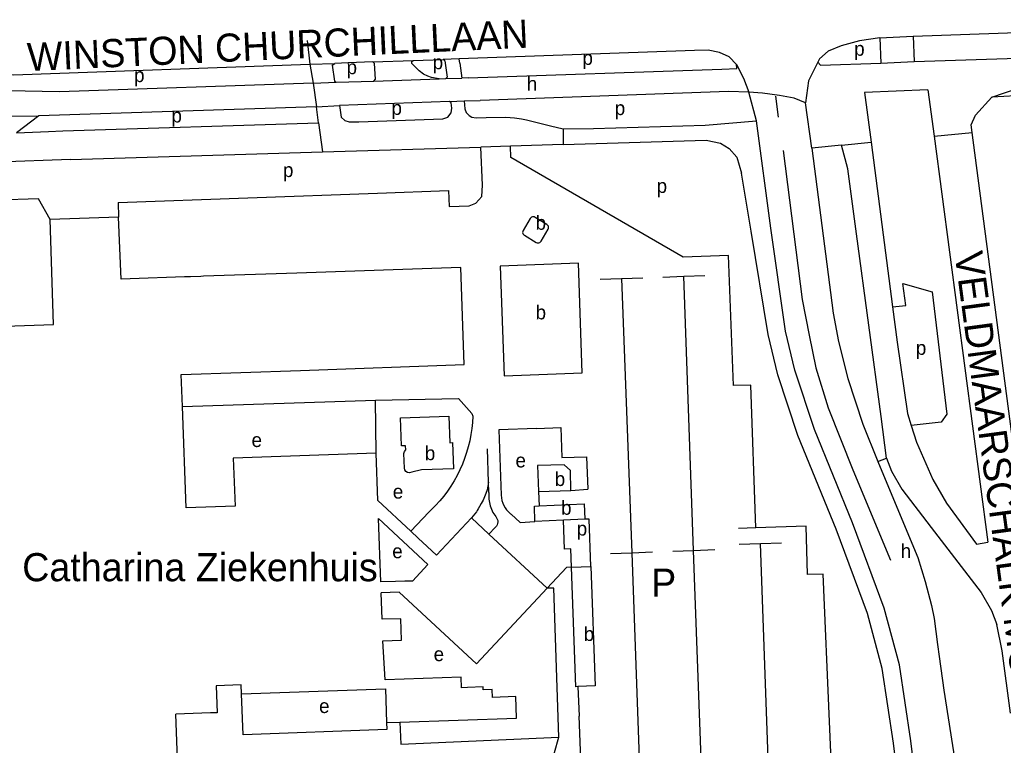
# Model space of a CAD drawing. Extents: x 159294 to 161936, y 384538 to 386517.
# Drawn here: x 160840.4 to 161120.1, y 386277.4 to 386483.9 of the extents above; entities that cross this region are included whole.
import ezdxf

# ---------------------------------------------------------------- set-up
doc = ezdxf.new("R2010")
doc.units = 0
for name, color, linetype in [('BLT_Basislijn', 7, 'Continuous'), ('BLT_Bebouwing', 7, 'Continuous'), ('BLT_Bebouwing_beschrifting', 7, 'Continuous'), ('BLT_Centroide', 7, 'Continuous'), ('BLT_Straatnaam_hoofdweg', 7, 'Continuous'), ('BLT_Tekst_parkeren', 7, 'Continuous'), ('BLT_Vlakafsluiter', 7, 'Continuous')]:
    doc.layers.add(name, color=color, linetype=linetype)

msp = doc.modelspace()

# ---------------------------------------------------------------- linework, layer by layer
at = {"layer": 'BLT_Basislijn'}
for p, q in [((161085.03, 386478.68), (161094.48, 386479.13)), ((161094.48, 386479.13), (161094.83, 386471.96)), ((161085.03, 386478.68), (161085.34, 386471.53)), ((160922.92, 386471.2), (160930.01, 386471.41)), ((160929.31, 386470.96), (160930.01, 386471.41)), ((160940.82, 386471.84), (160933.85, 386471.57)), ((160940.82, 386471.84), (160952.31, 386472.22)), ((160952.31, 386472.22), (160960.85, 386472.53)), ((160965.42, 386472.68), (160960.85, 386472.53)), ((160961.33, 386472.16), (160960.85, 386472.53)), ((160961.33, 386472.16), (160962.02, 386467.55)), ((160965.58, 386471.53), (160965.42, 386472.68)), ((161067.39, 386471.8), (161068.19, 386470.95)), ((161068.19, 386470.95), (161085.34, 386471.53)), ((161085.34, 386471.53), (161094.83, 386471.96)), ((160923.87, 386465.82), (160930.39, 386466.04)), ((160930.39, 386466.04), (160941.1, 386466.4)), ((160941.1, 386466.4), (160959.76, 386467.06)), ((160959.76, 386467.06), (160961.59, 386467.13)), ((160962.02, 386467.55), (160961.59, 386467.13)), ((160961.59, 386467.13), (160966.18, 386467.26)), ((160967.93, 386467.32), (160966.18, 386467.26)), ((161049.99, 386455.07), (161047.78, 386463.2)), ((161055.34, 386462.07), (161056.13, 386456.14)), ((161098.68, 386463.93), (161100.43, 386450.73)), ((160924.85, 386459.04), (160931.4, 386459.49)), ((160962.67, 386460.58), (160931.4, 386459.49)), ((160962.67, 386460.58), (160966.83, 386460.73)), ((160966.83, 386460.73), (160971.37, 386460.89)), ((161065.67, 386447.34), (161063.85, 386460.23)), ((160838.19, 386456.38), (160845.85, 386456.53)), ((161111.25, 386451.79), (161110.97, 386453.95)), ((160994.99, 386452.82), (160994.99, 386448.34)), ((161124.87, 386348.64), (161111.25, 386451.79)), ((160994.99, 386448.34), (160979.98, 386447.9)), ((161082.53, 386448.98), (161088.67, 386402.18)), ((161100.43, 386450.73), (161115.75, 386335.22)), ((160854.9, 386444.07), (160926.51, 386446.24)), ((160926.51, 386446.24), (160971.6, 386447.61)), ((160979.98, 386447.9), (160971.6, 386447.61)), ((160972.05, 386436.82), (160971.6, 386447.61)), ((160854.9, 386444.07), (160765.92, 386440.98)), ((160868.43, 386431.86), (160942.16, 386434.52)), ((160971.82, 386433.6), (160972.05, 386436.82)), ((160845.82, 386432.89), (160832.39, 386432.44)), ((160849.06, 386426.97), (160845.82, 386432.89)), ((160868.43, 386431.86), (160868.58, 386427.65)), ((160968.21, 386430.89), (160970.1, 386431.69)), ((160970.1, 386431.69), (160971.82, 386433.6)), ((161005.52, 386410.05), (161011.57, 386410.25)), ((161011.57, 386410.25), (161017.62, 386410.46)), ((161011.57, 386410.25), (161014.46, 386332.22)), ((161023.31, 386410.64), (161029.25, 386410.85)), ((161029.25, 386410.85), (161035.22, 386411.05)), ((161032.08, 386332.89), (161029.25, 386410.85)), ((161088.67, 386402.18), (161089.99, 386392.15)), ((160886.71, 386373.83), (160941.65, 386375.63)), ((160941.79, 386360.54), (160941.65, 386375.63)), ((160987.36, 386367.58), (160994.29, 386367.84)), ((160973.72, 386352.27), (160973.46, 386361.73)), ((160973.8, 386349.38), (160973.72, 386352.27)), ((160997.2, 386349.92), (161001.95, 386350.3)), ((160956.76, 386343.75), (160951.62, 386338.37)), ((160974.97, 386343.67), (160975.81, 386342.49)), ((160975.65, 386339.38), (160973.86, 386337.5)), ((161049.76, 386339.29), (161044.82, 386339.11)), ((161045.01, 386334.63), (161051.06, 386334.82)), ((161051.06, 386334.82), (161057.1, 386335.01)), ((161054.18, 386249.31), (161051.06, 386334.82)), ((161008.45, 386331.99), (161014.46, 386332.22)), ((161014.46, 386332.22), (161020.4, 386332.44)), ((161014.46, 386332.22), (161017.59, 386247.52)), ((161026.14, 386332.67), (161032.08, 386332.89)), ((161032.08, 386332.89), (161038.09, 386333.11)), ((161035.12, 386248.99), (161032.08, 386332.89)), ((161000.07, 386270.62), (160999.49, 386285.69))]:
    msp.add_line(p, q, dxfattribs=at)
for points in [[(161094.48, 386479.13), (161177.69, 386482.07)], [(161085.03, 386478.68), (161079.27, 386477.83), (161074, 386476.38), (161070.38, 386474.9), (161067.85, 386472.76), (161067.39, 386471.8)], [(161044.29, 386471.14), (161042.23, 386473.32), (161039.45, 386474.53), (161036.2, 386475.17), (161032.32, 386475.06), (160965.42, 386472.68)], [(161094.83, 386471.96), (161162.49, 386474.14)], [(160812.98, 386466.99), (160825.08, 386470.31), (160836.34, 386468.32), (160838.69, 386468.13), (160922.92, 386471.2)], [(160922.92, 386471.2), (160923.87, 386465.82)], [(160929.31, 386470.96), (160929.93, 386466.41), (160930.39, 386466.04)], [(160933.85, 386471.57), (160930.01, 386471.41)], [(160941.1, 386466.4), (160941.58, 386466.93), (160941.34, 386471.36), (160940.82, 386471.84)], [(160959.76, 386467.06), (160957.58, 386467.37), (160956.45, 386467.75), (160955.25, 386468.39), (160954, 386469.33), (160951.98, 386471.39), (160951.94, 386472), (160952.31, 386472.22)], [(160965.58, 386471.53), (160966.18, 386467.26)], [(161040.14, 386469.8), (161044.33, 386469.95), (161044.29, 386471.14)], [(160967.93, 386467.32), (161040.14, 386469.8)], [(160923.87, 386465.82), (160851.72, 386463.33), (160837.06, 386463.6), (160820.78, 386465.46), (160812.98, 386466.99)], [(161116.88, 386461.78), (161124.39, 386464.35), (161139.29, 386466.08), (161175.96, 386467.11)], [(161047.78, 386463.2), (161042.03, 386463.4), (160971.37, 386460.89)], [(161098.68, 386463.93), (161080.68, 386463.11), (161082.53, 386448.98)], [(161164.89, 386463.98), (161137.15, 386462.91), (161116.88, 386461.78)], [(160931.4, 386459.49), (160931.88, 386456.08), (160932.9, 386455.14), (160934.11, 386454.81), (160936.9, 386454.84), (160960.77, 386455.62), (160962.17, 386456.1), (160963.15, 386457.36), (160963.32, 386458.66), (160963.09, 386460.21), (160962.67, 386460.58)], [(160966.83, 386460.73), (160967.04, 386458.46), (160967.43, 386457.48), (160968.28, 386456.59), (160968.99, 386456.15), (160970.25, 386455.93), (160973.1, 386456.03), (160978.71, 386456.09), (160981.13, 386455.96), (160983.1, 386455.68), (160984.57, 386455.33), (160986.04, 386454.97), (160991.34, 386453.7), (160994.99, 386452.82)], [(161110.97, 386453.95), (161112.24, 386456.71), (161116.88, 386461.78)], [(160845.85, 386456.53), (160839.52, 386451.67), (160848.66, 386452.07), (160852.71, 386452.23), (160925.44, 386454.53)], [(160924.85, 386459.04), (160845.85, 386456.53)], [(160925.44, 386454.53), (160924.85, 386459.04)], [(160994.99, 386452.82), (161003.63, 386452.9), (161035.39, 386453.88), (161049.99, 386455.07)], [(161097.82, 386246.6), (161093.83, 386278.67), (161090.59, 386300.32), (161086.27, 386316.48), (161077.25, 386340.71), (161066.41, 386367.3), (161060.83, 386384.16), (161058.19, 386395.24), (161054, 386424.53), (161049.99, 386455.07)], [(160994.99, 386448.34), (161035.63, 386449.58), (161039.74, 386448.74), (161042.15, 386447.17), (161044.32, 386444.71), (161045.69, 386440.22)], [(161074.15, 386448.15), (161065.67, 386447.34)], [(161086.95, 386359.14), (161085.36, 386371.01), (161078.38, 386422.92), (161075.89, 386441.43), (161074.15, 386448.15)], [(161029.09, 386416.33), (160980.08, 386444.62), (160979.98, 386447.9)], [(161057.52, 386446.66), (161062.91, 386404.21), (161064.95, 386394.12), (161066.84, 386384.78), (161070.35, 386373.44), (161077.37, 386355.81), (161088.03, 386330.14)], [(161065.67, 386447.34), (161071.79, 386400.4), (161073.28, 386392.35), (161075.89, 386381.77), (161080.21, 386368.74), (161084.5, 386358.14)], [(161093.31, 386242.94), (161088.88, 386277.99), (161085.68, 386299.3), (161081.5, 386314.96), (161072.59, 386338.9), (161061.72, 386365.57), (161056.02, 386382.8), (161053.28, 386394.26), (161048.48, 386423.72), (161045.69, 386440.22)], [(160942.16, 386434.52), (160962.33, 386435.24), (160962.59, 386430.7), (160968.21, 386430.89)], [(161042.01, 386416.74), (161029.09, 386416.33)], [(161049.76, 386339.29), (161048.33, 386379.88), (161043.39, 386379.74), (161042.01, 386416.74)], [(161088.67, 386402.18), (161092.43, 386402.57), (161091.61, 386408.76), (161099.9, 386406.42), (161104.1, 386371.6), (161102.5, 386369.38), (161093.98, 386368.37)], [(161089.99, 386392.15), (161092.87, 386371.86), (161093.98, 386368.37)], [(160941.65, 386375.63), (160965.17, 386376.07), (160969.01, 386371.81), (160969.27, 386371.05)], [(160969.27, 386371.05), (160969.17, 386369.3), (160969, 386367.55), (160968.75, 386365.81), (160968.42, 386364.08), (160968.01, 386362.37), (160967.52, 386360.68), (160966.96, 386359.02), (160966.32, 386357.38), (160965.61, 386355.78), (160964.83, 386354.21), (160963.97, 386352.67), (160963.05, 386351.18), (160962.06, 386349.73), (160961, 386348.32), (160959.88, 386346.97), (160958.7, 386345.66), (160957.46, 386344.42), (160956.76, 386343.75)], [(160987.36, 386367.58), (160976.64, 386367.19), (160977.32, 386348.54)], [(160994.29, 386367.84), (160994.61, 386359.26), (161001.65, 386359.47), (161001.95, 386350.3)], [(161093.98, 386368.37), (161095.48, 386363.66), (161100.06, 386353.06), (161104, 386346.3), (161112.53, 386334.61), (161115.75, 386335.22)], [(161084.5, 386358.14), (161086.95, 386359.14)], [(161086.95, 386359.14), (161088.33, 386355.43), (161091.28, 386350.29), (161099.65, 386339.38), (161113.82, 386320.91), (161116.78, 386315.77), (161118.34, 386311.81)], [(161084.5, 386358.14), (161091.79, 386340.58), (161095.85, 386330.81), (161097.96, 386324.05), (161099.73, 386317.2), (161100.43, 386313.45), (161101.44, 386306.14), (161101.91, 386302.7), (161103.23, 386293.13), (161106.93, 386269.45)], [(160973.72, 386352.27), (160973.56, 386351.18), (160973.33, 386350.13), (160973.03, 386349.1), (160972.64, 386348.1), (160972.19, 386347.13), (160971.66, 386346.2), (160971.14, 386345.36), (160970.79, 386344.66), (160970.55, 386344.18), (160970.38, 386343.87), (160968.87, 386342.17)], [(160973.8, 386349.38), (160973.8, 386348.41), (160973.87, 386347.43), (160974.02, 386346.47), (160974.26, 386345.53), (160974.57, 386344.61), (160974.97, 386343.67)], [(160977.32, 386348.54), (160977.4, 386347.79), (160977.55, 386347.05), (160977.78, 386346.33), (160978.09, 386345.64), (160978.47, 386344.99), (160978.91, 386344.38), (160979.42, 386343.82), (160979.98, 386343.32), (160980.18, 386343.16), (160982.72, 386340.79), (160986.95, 386341.07)], [(160987.96, 386349.66), (160988.16, 386345.56)], [(160975.81, 386342.49), (160976.06, 386342.16), (160976.25, 386341.79), (160976.36, 386341.38), (160976.39, 386340.97), (160976.34, 386340.55), (160976.21, 386340.16), (160976.01, 386339.79), (160975.74, 386339.47), (160975.65, 386339.38)], [(160997.31, 386328.07), (160997.12, 386333.32), (160995.34, 386333.25), (160995.08, 386341.45)], [(161002.84, 386328.26), (161002.35, 386341.77), (161001.16, 386341.73)], [(161072.55, 386242.24), (161068.95, 386326.09), (161064.5, 386325.98), (161064.04, 386339.75), (161049.76, 386339.29)], [(160997.31, 386328.07), (160995.91, 386328.02), (160990.4, 386322.11)], [(160993.78, 386279.7), (160992.29, 386322.16), (160990.4, 386322.11)], [(161122.2, 386286.56), (161119.85, 386304.32), (161118.34, 386311.81)], [(160944.78, 386283.87), (160944.85, 386281.93), (160903.97, 386280.44), (160903.55, 386292.04)], [(160999.17, 386294.13), (160999.49, 386285.69)], [(160948.57, 386284), (160948.78, 386277.77), (160993.78, 386279.7)]]:
    msp.add_lwpolyline(points, dxfattribs=at)
at = {"layer": 'BLT_Bebouwing'}
for p, q in [((160985.6, 386427.25), (160983.58, 386423.85)), ((160990.35, 386425.63), (160987, 386427.62)), ((160988.69, 386420.88), (160990.69, 386424.26)), ((160983.94, 386422.52), (160987.3, 386420.51)), ((160966.85, 386385.74), (160965.87, 386413.35)), ((160892.69, 386410.86), (160891.94, 386410.84)), ((160886.71, 386373.83), (160886.38, 386382.88)), ((160887.79, 386344.98), (160886.71, 386373.83)), ((160941.79, 386360.54), (160901.14, 386359.08)), ((160901.14, 386359.08), (160901.69, 386345.5)), ((160942.28, 386347.03), (160941.79, 386360.54)), ((160987.69, 386356.98), (160987.96, 386349.66)), ((160987.96, 386349.66), (160997.2, 386349.92)), ((160901.69, 386345.5), (160887.79, 386344.98)), ((160956.53, 386328.9), (160942.47, 386341.92)), ((160943.13, 386323.92), (160942.47, 386341.92)), ((160958.94, 386331.49), (160968.87, 386342.17)), ((160968.87, 386342.17), (160973.86, 386337.5)), ((160995.08, 386341.45), (160986.95, 386341.07)), ((161001.16, 386341.73), (160995.08, 386341.45)), ((160953.73, 386336.32), (160956.28, 386334.01)), ((160973.86, 386337.5), (160990.4, 386322.11)), ((160956.28, 386334.01), (160958.94, 386331.49)), ((160952.1, 386324.13), (160956.53, 386328.9)), ((160948.39, 386321.03), (160943.24, 386320.8)), ((160894.74, 386286.63), (160884.87, 386286.28)), ((160885.3, 386273.45), (160884.87, 386286.28)), ((160896.55, 386286.7), (160894.74, 386286.63)), ((160944.78, 386283.87), (160948.57, 386284)), ((160948.57, 386284), (160981.75, 386285.13))]:
    msp.add_line(p, q, dxfattribs=at)
for points in [[(160833.24, 386401.41), (160833.42, 386396.55), (160850.07, 386397.15), (160849.06, 386426.97)], [(160868.58, 386427.65), (160849.06, 386426.97)], [(160871.86, 386410.15), (160869.28, 386410.06), (160868.58, 386427.65)], [(160987, 386427.62), (160986.76, 386427.75), (160986.49, 386427.81), (160986.22, 386427.78), (160985.97, 386427.68), (160985.76, 386427.51), (160985.61, 386427.28), (160985.6, 386427.25)], [(160983.58, 386423.85), (160983.47, 386423.59), (160983.44, 386423.32), (160983.49, 386423.05), (160983.62, 386422.8), (160983.8, 386422.61), (160983.94, 386422.52)], [(160990.69, 386424.26), (160990.8, 386424.52), (160990.83, 386424.8), (160990.78, 386425.08), (160990.66, 386425.33), (160990.47, 386425.54), (160990.35, 386425.63)], [(160987.3, 386420.51), (160987.54, 386420.39), (160987.81, 386420.33), (160988.08, 386420.36), (160988.33, 386420.47), (160988.53, 386420.64), (160988.68, 386420.86), (160988.69, 386420.88)], [(160965.87, 386413.35), (160919.29, 386411.7), (160892.69, 386410.86)], [(160891.94, 386410.84), (160889.02, 386410.74), (160887.26, 386410.69), (160871.86, 386410.15)], [(160886.38, 386382.88), (160920.27, 386384.09), (160966.85, 386385.74)], [(160997.2, 386349.92), (160997.03, 386355.63), (160995.22, 386357.24), (160987.69, 386356.98)], [(160942.28, 386347.03), (160951.62, 386338.37)], [(160986.95, 386341.07), (160986.78, 386345.49), (160988.16, 386345.56)], [(160988.16, 386345.56), (161000.95, 386346.16), (161001.16, 386341.73)], [(160951.62, 386338.37), (160953.73, 386336.32)], [(160997.31, 386328.07), (161002.84, 386328.26)], [(160999.17, 386294.13), (160998.58, 386294.1), (160997.31, 386328.07)], [(161002.84, 386328.26), (161004.05, 386294.31), (160999.17, 386294.13)], [(160952.1, 386324.13), (160949.91, 386324.12), (160947.27, 386324.05), (160943.13, 386323.92)], [(160967.75, 386293.87), (160966.07, 386293.81), (160965.97, 386296.81), (160944.36, 386296.07), (160943.74, 386307.15), (160949.03, 386307.34), (160948.81, 386313.44), (160943.52, 386313.27), (160943.24, 386320.8)], [(160990.4, 386322.11), (160970.35, 386300.59), (160948.39, 386321.03)], [(160903.55, 386292.04), (160903.45, 386294.59), (160896.32, 386294.37), (160896.55, 386286.7)], [(160903.55, 386292.04), (160944.45, 386293.52), (160944.78, 386283.87)], [(160981.54, 386291.26), (160974.89, 386291.04), (160974.82, 386293.33), (160972.24, 386293.24), (160972.21, 386294.02), (160967.75, 386293.87)], [(160981.75, 386285.13), (160981.54, 386291.26)]]:
    msp.add_lwpolyline(points, dxfattribs=at)
for points in [[(160999.33, 386414.58), (160977.05, 386413.75), (160978.21, 386382.54), (161000.42, 386383.36)], [(160948.7, 386370.62), (160962.47, 386371.1), (160962.76, 386363.51), (160963.5, 386363.54), (160963.78, 386356.11), (160954.68, 386355.76), (160951.96, 386355.09), (160951.3, 386354.94), (160950.68, 386355.07), (160950.25, 386355.35), (160949.95, 386355.78), (160949.82, 386356.26), (160949.68, 386360.44), (160949.82, 386361.03), (160950.22, 386361.48), (160950.18, 386362.66), (160949, 386362.62)]]:
    msp.add_lwpolyline(points, close=True, dxfattribs=at)
at = {"layer": 'BLT_Vlakafsluiter'}
for p, q in [((160922.17, 386477.94), (160922.92, 386471.2)), ((160923.87, 386465.82), (160924.85, 386459.04)), ((160925.44, 386454.53), (160926.51, 386446.24)), ((161100.43, 386450.73), (161111.25, 386451.79)), ((161074.15, 386448.15), (161082.53, 386448.98)), ((160991.07, 386270.26), (160993.78, 386279.7))]:
    msp.add_line(p, q, dxfattribs=at)
for points in [[(161044.29, 386471.14), (161046.29, 386467.2), (161047.78, 386463.2)], [(161067.39, 386471.8), (161064.77, 386466.5), (161063.85, 386460.23)], [(161063.85, 386460.23), (161060.68, 386461.5), (161056.45, 386462.28), (161051.66, 386462.98), (161047.78, 386463.2)]]:
    msp.add_lwpolyline(points, dxfattribs=at)

# ---------------------------------------------------------------- texts
at = {"layer": 'BLT_Bebouwing_beschrifting'}
msp.add_text('Catharina Ziekenhuis', height=8, dxfattribs=at).set_placement((160841.15, 386324.1))
at = {"layer": 'BLT_Centroide'}
for s, p in [('p', (161077.74, 386473.6)), ('p', (161000.47, 386471)), ('p', (160933.39, 386468.34)), ('p', (160957.87, 386469.77)), ('p', (160872.95, 386466.11)), ('h', (160984.63, 386463.62)), ('p', (160946.16, 386456.77)), ('p', (161009.64, 386456.72)), ('p', (160883.6, 386454.61)), ('p', (160915.3, 386439.09)), ('p', (161021.56, 386434.57)), ('b', (160987.14, 386424.08)), ('b', (160987.14, 386398.6)), ('p', (161095.27, 386388.5)), ('e', (160906.37, 386362.28)), ('b', (160955.64, 386358.54)), ('e', (160981.43, 386356.48)), ('b', (160992.57, 386351.19)), ('e', (160946.54, 386347.61)), ('b', (160994.38, 386343.01)), ('p', (160998.83, 386337.09)), ('e', (160946.37, 386330.65)), ('h', (161090.95, 386330.71)), ('b', (161000.82, 386307.1)), ('e', (160958.15, 386301.37)), ('e', (160925.58, 386286.6))]:
    msp.add_text(s, height=4, dxfattribs=at).set_placement(p)
at = {"layer": 'BLT_Straatnaam_hoofdweg'}
for s, height, rotation, p in [('WINSTON CHURCHILLLAAN', 8, 2.6938, (160842.74, 386469.21)), ('VELDMAARSCHALK MONTGOMERYLAAN', 7.9999, 277.6475, (161106.24, 386417.38))]:
    msp.add_text(s, height=height, rotation=rotation, dxfattribs=at).set_placement(p)
at = {"layer": 'BLT_Tekst_parkeren'}
msp.add_text('P', height=8, dxfattribs=at).set_placement((161019.99, 386319.7))

doc.saveas('drawing.dxf')
